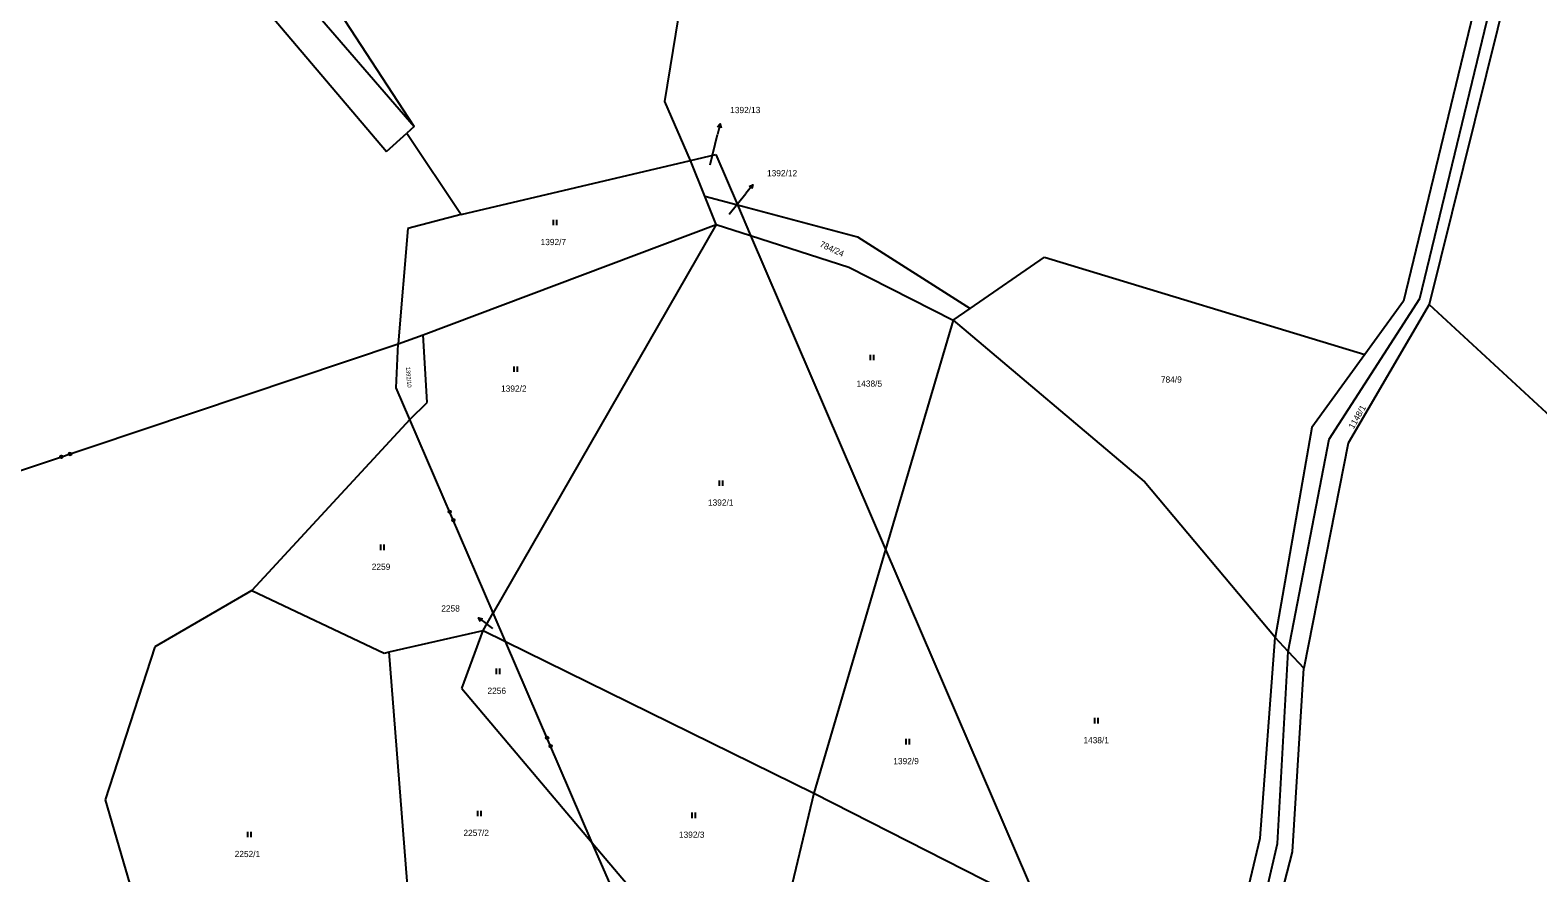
# Model space of a CAD drawing. Extents: x -747792 to -745414, y -1093712 to -1091463.
# Drawn here: x -746371.5 to -746166, y -1092420.5 to -1092305.6 of the extents above; entities that cross this region are included whole.
import ezdxf

# ---------------------------------------------------------------- set-up
doc = ezdxf.new("R2010")
doc.units = 0
for name, color, linetype in [('Pracovní_bod JDTM STC_VC', 7, 'Continuous'), ('Pracovní_bod JDTM STC_VC - číslo', 7, 'Continuous'), ('Pracovní_bod NN - výška', 7, 'Continuous'), ('Pracovní_bod polohopisu - výška', 7, 'Continuous')]:
    doc.layers.add(name, color=color, linetype=linetype)

msp = doc.modelspace()

# ---------------------------------------------------------------- linework, layer by layer
at = {"layer": 'Pracovní_bod JDTM STC_VC - číslo'}
for points in [[(-746300.23, -1092331.42), (-746300.23, -1092332.17)], [(-746299.73, -1092332.17), (-746299.73, -1092331.42)], [(-746256.99, -1092349.81), (-746256.99, -1092350.56)], [(-746256.49, -1092350.56), (-746256.49, -1092349.81)], [(-746305.57, -1092351.41), (-746305.57, -1092352.16)], [(-746305.07, -1092352.16), (-746305.07, -1092351.41)], [(-746277.57, -1092366.95), (-746277.57, -1092367.7)], [(-746277.07, -1092367.7), (-746277.07, -1092366.95)], [(-746323.78, -1092375.7), (-746323.78, -1092376.45)], [(-746323.28, -1092376.45), (-746323.28, -1092375.7)], [(-746308, -1092392.61), (-746308, -1092393.36)], [(-746307.5, -1092393.36), (-746307.5, -1092392.61)], [(-746226.4, -1092399.34), (-746226.4, -1092400.09)], [(-746225.9, -1092400.09), (-746225.9, -1092399.34)], [(-746252.12, -1092402.2), (-746252.12, -1092402.95)], [(-746251.62, -1092402.95), (-746251.62, -1092402.2)], [(-746310.52, -1092411.99), (-746310.52, -1092412.74)], [(-746310.02, -1092412.74), (-746310.02, -1092411.99)], [(-746281.31, -1092412.24), (-746281.31, -1092412.99)], [(-746280.81, -1092412.99), (-746280.81, -1092412.24)], [(-746341.87, -1092414.87), (-746341.87, -1092415.62)], [(-746341.37, -1092415.62), (-746341.37, -1092414.87)]]:
    msp.add_lwpolyline(points, dxfattribs=at)
at = {"layer": 'Pracovní_bod NN - výška'}
for points in [[(-746319.16, -1092318.69), (-746351.76, -1092268.74)], [(-746285.01, -1092315.29), (-746277.46, -1092269.05)], [(-746359, -1092279.59), (-746322.96, -1092322.12)], [(-746168.37, -1092292.92), (-746180.8, -1092342.97)], [(-746173.44, -1092297.58), (-746184.29, -1092342.49)], [(-746182.04, -1092342.14), (-746171.2, -1092297.21)], [(-746334.68, -1092300.72), (-746319.16, -1092318.69)], [(-746334.68, -1092300.72), (-746319.16, -1092318.69)], [(-746281.5, -1092323.32), (-746285.01, -1092315.29)], [(-746319.16, -1092318.69), (-746320.17, -1092319.6)], [(-746319.16, -1092318.69), (-746320.17, -1092319.6)], [(-746322.96, -1092322.12), (-746320.17, -1092319.6)], [(-746320.17, -1092319.6), (-746312.78, -1092330.71)], [(-746320.17, -1092319.6), (-746312.78, -1092330.71)], [(-746312.78, -1092330.71), (-746281.5, -1092323.32)], [(-746281.5, -1092323.32), (-746278.04, -1092322.51)], [(-746279.54, -1092328.18), (-746281.5, -1092323.32)], [(-746278.04, -1092322.51), (-746275.1, -1092329.37)], [(-746277.98, -1092332.04), (-746279.54, -1092328.18)], [(-746279.54, -1092328.18), (-746275.1, -1092329.37)], [(-746275.1, -1092329.37), (-746258.71, -1092333.74)], [(-746275.1, -1092329.37), (-746273.3, -1092333.55)], [(-746312.78, -1092330.71), (-746320.02, -1092332.58)], [(-746312.78, -1092330.71), (-746320.02, -1092332.58)], [(-746320.02, -1092332.58), (-746321.34, -1092348.34)], [(-746320.02, -1092332.58), (-746321.34, -1092348.34)], [(-746317.92, -1092347.08), (-746277.98, -1092332.04)], [(-746277.98, -1092332.04), (-746308.39, -1092385.01)], [(-746277.98, -1092332.04), (-746273.3, -1092333.55)], [(-746273.3, -1092333.55), (-746254.89, -1092376.39)], [(-746273.3, -1092333.55), (-746259.91, -1092337.87)], [(-746258.71, -1092333.74), (-746243.37, -1092343.5)], [(-746259.91, -1092337.87), (-746245.68, -1092345.09)], [(-746243.37, -1092343.5), (-746233.22, -1092336.51)], [(-746233.22, -1092336.51), (-746189.57, -1092349.77)], [(-746194.43, -1092361.35), (-746182.04, -1092342.14)], [(-746245.68, -1092345.09), (-746243.37, -1092343.5)], [(-746180.8, -1092342.97), (-746191.82, -1092361.88)], [(-746184.29, -1092342.49), (-746189.57, -1092349.77)], [(-746180.8, -1092342.97), (-746105.15, -1092412.77)], [(-746245.68, -1092345.09), (-746254.89, -1092376.39)], [(-746245.68, -1092345.09), (-746219.63, -1092367.08)], [(-746321.34, -1092348.34), (-746317.92, -1092347.08)], [(-746317.39, -1092356.33), (-746317.92, -1092347.08)], [(-746412.03, -1092378.75), (-746321.34, -1092348.34)], [(-746321.61, -1092354.33), (-746321.34, -1092348.34)], [(-746321.61, -1092354.33), (-746321.34, -1092348.34)], [(-746189.57, -1092349.77), (-746196.79, -1092359.72)], [(-746319.76, -1092358.63), (-746321.61, -1092354.33)], [(-746319.76, -1092358.63), (-746321.61, -1092354.33)], [(-746319.76, -1092358.63), (-746317.39, -1092356.33)], [(-746319.76, -1092358.63), (-746341.3, -1092381.95)], [(-746308.39, -1092385.01), (-746319.76, -1092358.63)], [(-746308.39, -1092385.01), (-746319.76, -1092358.63)], [(-746196.79, -1092359.72), (-746201.79, -1092388.38)], [(-746200, -1092390.3), (-746194.43, -1092361.35)], [(-746191.82, -1092361.88), (-746197.89, -1092392.56)], [(-746367.24, -1092363.56), (-746367.12, -1092363.62), (-746367.08, -1092363.75), (-746367.14, -1092363.87), (-746367.27, -1092363.91), (-746367.39, -1092363.85), (-746367.43, -1092363.73), (-746367.37, -1092363.61), (-746367.24, -1092363.56), (-746367.24, -1092363.58), (-746367.36, -1092363.62), (-746367.38, -1092363.67), (-746367.19, -1092363.61), (-746367.14, -1092363.63), (-746367.41, -1092363.72), (-746367.39, -1092363.76), (-746367.13, -1092363.67), (-746367.11, -1092363.71), (-746367.38, -1092363.8), (-746367.37, -1092363.84), (-746367.1, -1092363.75), (-746367.13, -1092363.8), (-746367.32, -1092363.86), (-746367.27, -1092363.89), (-746367.15, -1092363.85)], [(-746366.06, -1092363.17), (-746365.94, -1092363.23), (-746365.89, -1092363.35), (-746365.95, -1092363.47), (-746366.08, -1092363.52), (-746366.2, -1092363.46), (-746366.25, -1092363.33), (-746366.19, -1092363.21), (-746366.06, -1092363.17), (-746366.07, -1092363.19), (-746366.18, -1092363.23), (-746366.2, -1092363.28), (-746366.02, -1092363.21), (-746365.96, -1092363.24), (-746366.23, -1092363.33), (-746366.22, -1092363.37), (-746365.95, -1092363.28), (-746365.94, -1092363.32), (-746366.2, -1092363.41), (-746366.19, -1092363.44), (-746365.93, -1092363.35), (-746365.95, -1092363.4), (-746366.14, -1092363.47), (-746366.09, -1092363.49), (-746365.98, -1092363.46)], [(-746201.79, -1092388.38), (-746219.63, -1092367.08)], [(-746314.5, -1092371.23), (-746314.46, -1092371.1), (-746314.33, -1092371.05), (-746314.21, -1092371.1), (-746314.15, -1092371.22), (-746314.2, -1092371.35), (-746314.33, -1092371.4), (-746314.45, -1092371.35), (-746314.5, -1092371.23), (-746314.48, -1092371.23), (-746314.43, -1092371.34), (-746314.38, -1092371.36), (-746314.46, -1092371.18), (-746314.44, -1092371.13), (-746314.33, -1092371.38), (-746314.29, -1092371.37), (-746314.4, -1092371.11), (-746314.37, -1092371.1), (-746314.25, -1092371.35), (-746314.22, -1092371.34), (-746314.33, -1092371.08), (-746314.28, -1092371.1), (-746314.2, -1092371.28), (-746314.18, -1092371.23), (-746314.22, -1092371.12)], [(-746314.5, -1092371.23), (-746314.46, -1092371.1), (-746314.33, -1092371.05), (-746314.21, -1092371.1), (-746314.15, -1092371.22), (-746314.2, -1092371.35), (-746314.33, -1092371.4), (-746314.45, -1092371.35), (-746314.5, -1092371.23), (-746314.48, -1092371.23), (-746314.43, -1092371.34), (-746314.38, -1092371.36), (-746314.46, -1092371.18), (-746314.44, -1092371.13), (-746314.33, -1092371.38), (-746314.29, -1092371.37), (-746314.4, -1092371.11), (-746314.37, -1092371.1), (-746314.25, -1092371.35), (-746314.22, -1092371.34), (-746314.33, -1092371.08), (-746314.28, -1092371.1), (-746314.2, -1092371.28), (-746314.18, -1092371.23), (-746314.22, -1092371.12)], [(-746314.01, -1092372.37), (-746313.96, -1092372.25), (-746313.84, -1092372.2), (-746313.71, -1092372.25), (-746313.66, -1092372.37), (-746313.71, -1092372.49), (-746313.83, -1092372.55), (-746313.96, -1092372.5), (-746314.01, -1092372.37), (-746313.99, -1092372.37), (-746313.94, -1092372.48), (-746313.89, -1092372.5), (-746313.97, -1092372.32), (-746313.95, -1092372.27), (-746313.84, -1092372.52), (-746313.8, -1092372.51), (-746313.91, -1092372.25), (-746313.87, -1092372.23), (-746313.76, -1092372.49), (-746313.73, -1092372.48), (-746313.84, -1092372.22), (-746313.79, -1092372.24), (-746313.71, -1092372.42), (-746313.69, -1092372.37), (-746313.73, -1092372.26)], [(-746314.01, -1092372.37), (-746313.96, -1092372.25), (-746313.84, -1092372.2), (-746313.71, -1092372.25), (-746313.66, -1092372.37), (-746313.71, -1092372.49), (-746313.83, -1092372.55), (-746313.96, -1092372.5), (-746314.01, -1092372.37), (-746313.99, -1092372.37), (-746313.94, -1092372.48), (-746313.89, -1092372.5), (-746313.97, -1092372.32), (-746313.95, -1092372.27), (-746313.84, -1092372.52), (-746313.8, -1092372.51), (-746313.91, -1092372.25), (-746313.87, -1092372.23), (-746313.76, -1092372.49), (-746313.73, -1092372.48), (-746313.84, -1092372.22), (-746313.79, -1092372.24), (-746313.71, -1092372.42), (-746313.69, -1092372.37), (-746313.73, -1092372.26)], [(-746254.89, -1092376.39), (-746264.66, -1092409.59)], [(-746254.89, -1092376.39), (-746233.88, -1092425.29)], [(-746341.3, -1092381.95), (-746354.51, -1092389.65)], [(-746341.3, -1092381.95), (-746323.26, -1092390.51)], [(-746309.76, -1092387.4), (-746308.39, -1092385.01)], [(-746306.71, -1092388.9), (-746308.39, -1092385.01)], [(-746306.71, -1092388.9), (-746308.39, -1092385.01)], [(-746322.58, -1092390.35), (-746309.76, -1092387.4)], [(-746312.69, -1092395.34), (-746309.76, -1092387.4)], [(-746309.76, -1092387.4), (-746306.71, -1092388.9)], [(-746294.88, -1092416.36), (-746306.71, -1092388.9)], [(-746306.71, -1092388.9), (-746264.66, -1092409.59)], [(-746294.88, -1092416.36), (-746306.71, -1092388.9)], [(-746203.8, -1092415.74), (-746201.79, -1092388.38)], [(-746200, -1092390.3), (-746201.79, -1092388.38)], [(-746354.51, -1092389.65), (-746361.32, -1092410.5)], [(-746323.26, -1092390.51), (-746322.58, -1092390.35)], [(-746319.46, -1092430.3), (-746322.58, -1092390.35)], [(-746201.46, -1092416.48), (-746200, -1092390.3)], [(-746200, -1092390.3), (-746197.89, -1092392.56)], [(-746199.41, -1092417.6), (-746197.89, -1092392.56)], [(-746312.69, -1092395.34), (-746294.88, -1092416.36)], [(-746301.22, -1092402.04), (-746301.18, -1092401.91), (-746301.05, -1092401.86), (-746300.93, -1092401.91), (-746300.87, -1092402.03), (-746300.92, -1092402.16), (-746301.05, -1092402.21), (-746301.17, -1092402.16), (-746301.22, -1092402.04), (-746301.2, -1092402.04), (-746301.15, -1092402.15), (-746301.1, -1092402.17), (-746301.18, -1092401.99), (-746301.16, -1092401.94), (-746301.05, -1092402.19), (-746301.01, -1092402.18), (-746301.12, -1092401.92), (-746301.09, -1092401.91), (-746300.97, -1092402.16), (-746300.94, -1092402.15), (-746301.05, -1092401.89), (-746301, -1092401.91), (-746300.92, -1092402.09), (-746300.9, -1092402.04), (-746300.94, -1092401.93)], [(-746301.22, -1092402.04), (-746301.18, -1092401.91), (-746301.05, -1092401.86), (-746300.93, -1092401.91), (-746300.87, -1092402.03), (-746300.92, -1092402.16), (-746301.05, -1092402.21), (-746301.17, -1092402.16), (-746301.22, -1092402.04), (-746301.2, -1092402.04), (-746301.15, -1092402.15), (-746301.1, -1092402.17), (-746301.18, -1092401.99), (-746301.16, -1092401.94), (-746301.05, -1092402.19), (-746301.01, -1092402.18), (-746301.12, -1092401.92), (-746301.09, -1092401.91), (-746300.97, -1092402.16), (-746300.94, -1092402.15), (-746301.05, -1092401.89), (-746301, -1092401.91), (-746300.92, -1092402.09), (-746300.9, -1092402.04), (-746300.94, -1092401.93)], [(-746300.73, -1092403.18), (-746300.68, -1092403.06), (-746300.56, -1092403.01), (-746300.43, -1092403.06), (-746300.38, -1092403.18), (-746300.43, -1092403.3), (-746300.55, -1092403.36), (-746300.68, -1092403.31), (-746300.73, -1092403.18), (-746300.71, -1092403.18), (-746300.66, -1092403.29), (-746300.61, -1092403.31), (-746300.69, -1092403.13), (-746300.67, -1092403.08), (-746300.56, -1092403.33), (-746300.52, -1092403.32), (-746300.63, -1092403.06), (-746300.59, -1092403.04), (-746300.48, -1092403.3), (-746300.45, -1092403.29), (-746300.56, -1092403.03), (-746300.51, -1092403.05), (-746300.43, -1092403.23), (-746300.41, -1092403.18), (-746300.45, -1092403.07)], [(-746300.73, -1092403.18), (-746300.68, -1092403.06), (-746300.56, -1092403.01), (-746300.43, -1092403.06), (-746300.38, -1092403.18), (-746300.43, -1092403.3), (-746300.55, -1092403.36), (-746300.68, -1092403.31), (-746300.73, -1092403.18), (-746300.71, -1092403.18), (-746300.66, -1092403.29), (-746300.61, -1092403.31), (-746300.69, -1092403.13), (-746300.67, -1092403.08), (-746300.56, -1092403.33), (-746300.52, -1092403.32), (-746300.63, -1092403.06), (-746300.59, -1092403.04), (-746300.48, -1092403.3), (-746300.45, -1092403.29), (-746300.56, -1092403.03), (-746300.51, -1092403.05), (-746300.43, -1092403.23), (-746300.41, -1092403.18), (-746300.45, -1092403.07)], [(-746264.66, -1092409.59), (-746272.58, -1092442.68)], [(-746264.66, -1092409.59), (-746233.88, -1092425.29)], [(-746361.32, -1092410.5), (-746355.77, -1092429.53)], [(-746209.09, -1092437.94), (-746203.8, -1092415.74)], [(-746292.19, -1092422.6), (-746294.88, -1092416.36)], [(-746294.88, -1092416.36), (-746272.58, -1092442.68)], [(-746292.19, -1092422.6), (-746294.88, -1092416.36)], [(-746204.38, -1092436.79), (-746199.41, -1092417.6)], [(-746204.28, -1092428.66), (-746201.46, -1092416.48)]]:
    msp.add_lwpolyline(points, dxfattribs=at)
at = {"layer": 'Pracovní_bod polohopisu - výška'}
for points in [[(-746277.8, -1092318.75), (-746277.43, -1092318.32), (-746277.31, -1092318.87)], [(-746277.43, -1092318.32), (-746277.79, -1092319.78)], [(-746278.8, -1092323.9), (-746277.79, -1092319.78)], [(-746273, -1092326.65), (-746273.94, -1092327.82)], [(-746273.51, -1092326.88), (-746273, -1092326.65), (-746273.12, -1092327.2)], [(-746276.22, -1092330.65), (-746273.94, -1092327.82)], [(-746310.4, -1092385.71), (-746309.19, -1092386.6)], [(-746310.14, -1092386.21), (-746310.4, -1092385.71), (-746309.85, -1092385.81)], [(-746308.46, -1092387.14), (-746309.19, -1092386.6)]]:
    msp.add_lwpolyline(points, dxfattribs=at)

# ---------------------------------------------------------------- texts
at = {"layer": 'Pracovní_bod JDTM STC_VC'}
for s, height, rotation, p in [('1392/13', 0.05, 313.236, (-746278.89, -1092323.81)), ('1392/12', 0.05, 317.7051, (-746276.31, -1092330.56)), ('784/24', 0.85, 335.123, (-746263.96, -1092335.03)), ('1392/10', 0.57, 274.0457, (-746320.29, -1092351.48)), ('1148/1', 0.85, 60.046, (-746191.09, -1092360.01))]:
    msp.add_text(s, height=height, rotation=rotation, dxfattribs=at).set_placement(p)
for s, height, p in [('1392/7', 0.85, (-746301.93, -1092334.87)), ('1392/2', 0.85, (-746307.32, -1092354.86)), ('1438/5', 0.85, (-746258.85, -1092354.18)), ('784/9', 0.85, (-746217.35, -1092353.62)), ('1392/1', 0.85, (-746279.11, -1092370.4)), ('2259', 0.85, (-746324.95, -1092379.15)), ('2258', 0.05, (-746308.54, -1092387.14)), ('2256', 0.85, (-746309.17, -1092396.06)), ('1438/1', 0.85, (-746227.92, -1092402.79)), ('1392/9', 0.85, (-746253.84, -1092405.65)), ('2257/2', 0.85, (-746312.45, -1092415.44)), ('1392/3', 0.85, (-746283.07, -1092415.69)), ('2252/1', 0.85, (-746343.64, -1092418.32))]:
    msp.add_text(s, height=height, dxfattribs=at).set_placement(p)
at = {"layer": 'Pracovní_bod polohopisu - výška'}
for s, p in [('1392/13', (-746276.08, -1092316.87)), ('1392/12', (-746271.06, -1092325.48)), ('2258', (-746315.47, -1092384.83))]:
    msp.add_text(s, height=0.85, dxfattribs=at).set_placement(p)

doc.saveas('drawing.dxf')
